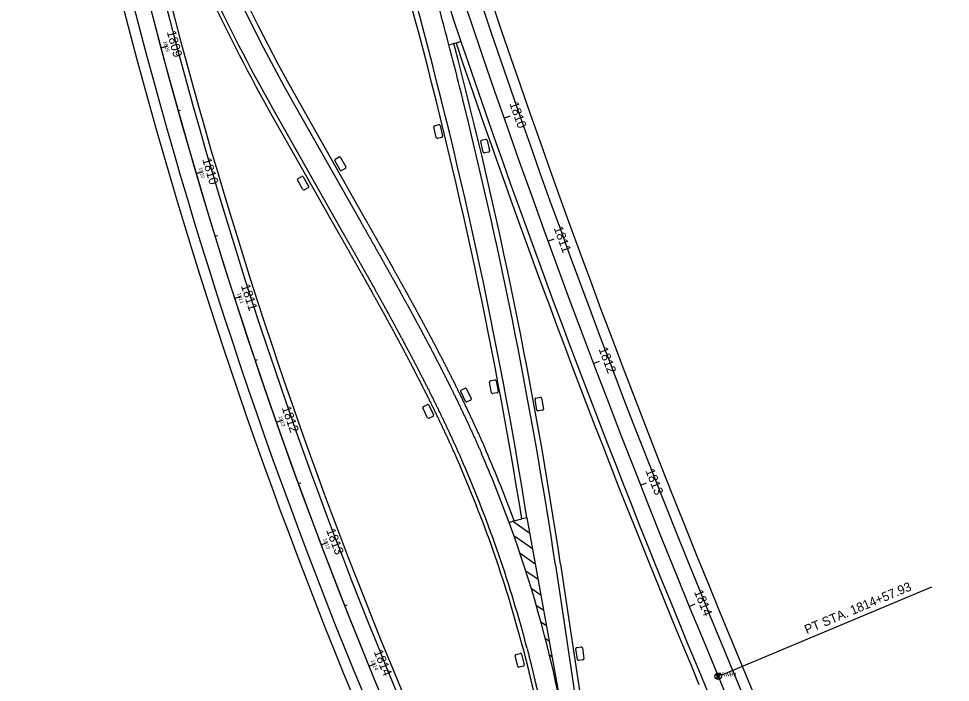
# Model space of a CAD drawing. Extents: x 8527 to 36635, y 12099 to 39012.
# Drawn here: x 20646 to 21360, y 34779 to 35288 of the extents above; entities that cross this region are included whole.
import ezdxf

# ---------------------------------------------------------------- set-up
doc = ezdxf.new("R2010")
doc.units = 0
for name, color, linetype in [('DR_P_Inlet_Protection', 7, 'Continuous'), ('GE_X_CL_20', 7, 'Continuous'), ('GK_Visualization', 7, 'Continuous'), ('MT_P_Dotted_Line', 7, 'Continuous'), ('MT_P_Text', 7, 'Continuous'), ('MT_P_Traffic_Attenuator', 7, 'Continuous'), ('PM_P_Transverse_Line', 7, 'Continuous'), ('PV_X_EOP', 7, 'Continuous'), ('PV_X_Shoulder', 7, 'Continuous'), ('SH_Cut_Line', 7, 'Continuous'), ('SH_Text', 7, 'Continuous')]:
    doc.layers.add(name, color=color, linetype=linetype)

msp = doc.modelspace()

# ---------------------------------------------------------------- linework, layer by layer
at = {"layer": 'DR_P_Inlet_Protection'}
msp.add_line((21182.19, 34784.02), (22003.54, 32822.13), dxfattribs=at)
for centre, radius, start, end in [((28229.01, 37734.18), 7639.44, 189.175, 202.716667), ((24529.94, 36271.9), 3906.53, 186.21667, 209.21667), ((24529.94, 36271.9), 3906.53, 191.33607, 209.21667)]:
    msp.add_arc(centre, radius, start, end, dxfattribs=at)
at = {"layer": 'GE_X_CL_20'}
for p, q in [((20755.34, 35265.23), (20757.27, 35265.75)), ((20768.53, 35217), (20770.46, 35217.55)), ((20782.34, 35168.95), (20784.26, 35169.51)), ((20796.76, 35121.08), (20798.68, 35121.67)), ((20811.8, 35073.39), (20813.7, 35074)), ((20827.44, 35025.9), (20829.34, 35026.54)), ((20843.69, 34978.62), (20845.58, 34979.28)), ((20860.55, 34931.54), (20862.43, 34932.23)), ((20878, 34884.69), (20879.87, 34885.4)), ((20896.06, 34838.06), (20897.92, 34838.8)), ((20914.71, 34791.67), (20916.56, 34792.43))]:
    msp.add_line(p, q, dxfattribs=at)
at = {"layer": 'GK_Visualization'}
for p, q in [((21183.75, 34784.02), (21180.63, 34784.02)), ((21180.86, 34782.69), (21183.53, 34785.36)), ((21180.86, 34785.36), (21183.53, 34782.69)), ((21182.19, 34785.58), (21182.19, 34782.46)), ((21182.19, 34784.02), (21938.59, 32977.27))]:
    msp.add_line(p, q, dxfattribs=at)
msp.add_arc((28229.01, 37734.18), 7639.44, 189.175, 202.716667, dxfattribs=at)
msp.add_arc((28229.01, 37734.18), 7639.44, 189.175, 202.716667, dxfattribs=at)
at = {"layer": 'MT_P_Dotted_Line'}
msp.add_line((21035.74, 34905.29), (21061.45, 34762.43), dxfattribs=at)
msp.add_arc((20125.43, 34573.33), 954.93, 11.42127, 20.11867, dxfattribs=at)
at = {"layer": 'MT_P_Text'}
for p, q in [((20755.34, 35265.23), (20760.17, 35266.52)), ((20782.34, 35168.95), (20787.14, 35170.36)), ((20811.8, 35073.39), (20816.56, 35074.92)), ((20843.69, 34978.62), (20848.41, 34980.27)), ((20878, 34884.69), (20882.68, 34886.46)), ((20914.71, 34791.67), (20919.33, 34793.57)), ((21182.19, 34784.02), (21938.59, 32977.27))]:
    msp.add_line(p, q, dxfattribs=at)
for centre, radius, start, end in [((28229.01, 37734.18), 7639.44, 189.175, 202.716667), ((24529.94, 36271.9), 3906.53, 186.21667, 209.21667)]:
    msp.add_arc(centre, radius, start, end, dxfattribs=at)
at = {"layer": 'MT_P_Traffic_Attenuator'}
for p, q in [((20981.38, 35268.89), (20979.81, 35268.47)), ((20861.46, 35223.01), (20911.92, 35133.96)), ((20841.45, 35211.67), (20891.91, 35122.62)), ((21035.74, 34905.29), (21031.79, 34904.66)), ((21022.09, 34901.79), (21025.84, 34903.17)), ((21061.5, 34869.77), (21067.12, 34832.37)), ((21067.12, 34832.37), (21100.09, 34612.83)), ((21200.64, 34791.75), (22021.99, 32829.86))]:
    msp.add_line(p, q, dxfattribs=at)
for centre, radius, start, end in [((28229.01, 37734.18), 7619.44, 191.815419, 202.716667), ((22104.16, 35927.29), 1428.39, 188.08556, 209.54167), ((24529.94, 36271.9), 3926.53, 191.34141, 209.21667), ((24529.94, 36271.9), 3890.53, 192.86631, 209.21667), ((22104.16, 35927.29), 1451.39, 200.88855, 209.54167), ((17264.37, 34299.46), 3815.72, 9.126, 15.41472), ((17264.37, 34299.46), 3839.72, 8.54167, 14.61747), ((28229.01, 37734.18), 7655.44, 198.78578, 202.716667), ((20125.43, 34573.33), 958.93, 20.11867, 23.54167), ((20111.51, 34565.44), 951.93, 14.54167, 23.54167)]:
    msp.add_arc(centre, radius, start, end, dxfattribs=at)
for points in [[(20911.92, 35133.96), (20913.25, 35131.61), (20914.59, 35129.26), (20915.92, 35126.91), (20917.25, 35124.56), (20918.58, 35122.21), (20919.92, 35119.85), (20921.25, 35117.5), (20922.58, 35115.15), (20923.91, 35112.79), (20925.24, 35110.44), (20926.56, 35108.08), (20927.89, 35105.72), (20929.22, 35103.37), (20930.54, 35101.01), (20931.87, 35098.65), (20933.19, 35096.29), (20934.51, 35093.93), (20935.83, 35091.57), (20937.15, 35089.21), (20938.47, 35086.84), (20939.78, 35084.48), (20941.1, 35082.11), (20942.41, 35079.75), (20943.72, 35077.38), (20945.03, 35075.01), (20946.33, 35072.64), (20947.63, 35070.26), (20948.93, 35067.89), (20950.23, 35065.51), (20951.53, 35063.14), (20952.82, 35060.76), (20954.11, 35058.38), (20955.4, 35056), (20956.68, 35053.61), (20957.96, 35051.23), (20959.24, 35048.84), (20960.52, 35046.45), (20961.79, 35044.06), (20963.05, 35041.66), (20964.32, 35039.27), (20965.58, 35036.87), (20966.84, 35034.47), (20968.09, 35032.07), (20969.34, 35029.67), (20970.59, 35027.26), (20971.83, 35024.85), (20973.07, 35022.44), (20974.3, 35020.03), (20975.53, 35017.61), (20976.75, 35015.19), (20977.97, 35012.77), (20979.19, 35010.35), (20980.4, 35007.93), (20981.6, 35005.5), (20982.8, 35003.07), (20984, 35000.63), (20985.19, 34998.2), (20986.38, 34995.76), (20987.56, 34993.32), (20988.73, 34990.87), (20989.9, 34988.43), (20991.06, 34985.98), (20992.22, 34983.52), (20993.37, 34981.07), (20994.52, 34978.61), (20995.66, 34976.15), (20996.79, 34973.68), (20997.92, 34971.21), (20999.04, 34968.74), (21000.15, 34966.27), (21001.26, 34963.79), (21002.36, 34961.31), (21003.46, 34958.83), (21004.54, 34956.35)], [(20891.91, 35122.62), (20893.24, 35120.27), (20894.58, 35117.92), (20895.91, 35115.57), (20897.24, 35113.22), (20898.57, 35110.87), (20899.9, 35108.52), (20901.23, 35106.16), (20902.56, 35103.81), (20903.89, 35101.46), (20905.22, 35099.11), (20906.55, 35096.75), (20907.87, 35094.4), (20909.2, 35092.05), (20910.52, 35089.69), (20911.84, 35087.34), (20913.16, 35084.98), (20914.48, 35082.62), (20915.8, 35080.27), (20917.12, 35077.91), (20918.43, 35075.55), (20919.74, 35073.19), (20921.06, 35070.83), (20922.36, 35068.47), (20923.67, 35066.1), (20924.97, 35063.74), (20926.28, 35061.38), (20927.58, 35059.01), (20928.87, 35056.64), (20930.17, 35054.27), (20931.46, 35051.9), (20932.75, 35049.53), (20934.03, 35047.16), (20935.32, 35044.78), (20936.6, 35042.41), (20937.87, 35040.03), (20939.15, 35037.65), (20940.42, 35035.27), (20941.68, 35032.89), (20942.95, 35030.5), (20944.21, 35028.12), (20945.46, 35025.73), (20946.72, 35023.34), (20947.96, 35020.95), (20949.21, 35018.55), (20950.45, 35016.16), (20951.68, 35013.76), (20952.92, 35011.36), (20954.14, 35008.96), (20955.37, 35006.55), (20956.58, 35004.15), (20957.8, 35001.74), (20959.01, 34999.33), (20960.21, 34996.92), (20961.41, 34994.5), (20962.61, 34992.08), (20963.79, 34989.66), (20964.98, 34987.24), (20966.16, 34984.82), (20967.33, 34982.39), (20968.5, 34979.96), (20969.66, 34977.53), (20970.81, 34975.09), (20971.97, 34972.65), (20973.11, 34970.21), (20974.25, 34967.77), (20975.38, 34965.32), (20976.51, 34962.88), (20977.63, 34960.42), (20978.74, 34957.97), (20979.85, 34955.51), (20980.95, 34953.05), (20982.04, 34950.59), (20983.13, 34948.13), (20984.21, 34945.65)], [(21032.94, 34804.46), (21033.61, 34801.85), (21034.28, 34799.24), (21034.94, 34796.62), (21035.59, 34794.01), (21036.23, 34791.39), (21036.87, 34788.77), (21037.5, 34786.15), (21038.12, 34783.53), (21038.74, 34780.91), (21039.35, 34778.28), (21039.96, 34775.66), (21040.56, 34773.03), (21041.15, 34770.4), (21041.73, 34767.77), (21042.31, 34765.13), (21042.89, 34762.5), (21043.46, 34759.86), (21044.02, 34757.23), (21044.57, 34754.59), (21045.13, 34751.95), (21045.67, 34749.31), (21046.21, 34746.67), (21046.75, 34744.02), (21047.28, 34741.38), (21047.8, 34738.73), (21048.32, 34736.09), (21048.84, 34733.44), (21049.35, 34730.79), (21049.85, 34728.14), (21050.36, 34725.49), (21050.85, 34722.84), (21051.35, 34720.19), (21051.83, 34717.53), (21052.32, 34714.88), (21052.8, 34712.22), (21053.27, 34709.57), (21053.75, 34706.91), (21054.22, 34704.25), (21054.68, 34701.6), (21055.14, 34698.94), (21055.6, 34696.28), (21056.05, 34693.62), (21056.51, 34690.96), (21056.95, 34688.29), (21057.4, 34685.63), (21057.84, 34682.97), (21058.28, 34680.3), (21058.72, 34677.64), (21059.15, 34674.98), (21059.58, 34672.31), (21060.01, 34669.65), (21060.44, 34666.98), (21060.87, 34664.31), (21061.29, 34661.65), (21061.71, 34658.98), (21062.13, 34656.31), (21062.54, 34653.64), (21062.96, 34650.97), (21063.37, 34648.3), (21063.78, 34645.63), (21064.19, 34642.96), (21064.6, 34640.29), (21065.01, 34637.62), (21065.42, 34634.95), (21065.82, 34632.28), (21066.23, 34629.61), (21066.63, 34626.94), (21067.04, 34624.27), (21067.44, 34621.6), (21067.84, 34618.92), (21068.24, 34616.25), (21068.65, 34613.58), (21069.05, 34610.91), (21069.45, 34608.23)]]:
    msp.add_spline(points, degree=3, dxfattribs=at)
at = {"layer": 'PM_P_Transverse_Line'}
for p, q in [((21037.87, 34893.48), (21024.59, 34902.71)), ((21039.99, 34881.67), (21025.77, 34891.56)), ((21042.12, 34869.86), (21030.46, 34877.96)), ((21044.24, 34858.05), (21034.86, 34864.57)), ((21046.37, 34846.24), (21038.98, 34851.38)), ((21048.49, 34834.43), (21042.84, 34838.36)), ((21050.62, 34822.62), (21046.45, 34825.51)), ((21052.74, 34810.81), (21049.83, 34812.83)), ((21054.86, 34799), (21052.99, 34800.31))]:
    msp.add_line(p, q, dxfattribs=at)
at = {"layer": 'PV_X_EOP'}
msp.add_arc((17264.37, 34299.46), 3835.72, 14.61747, 15.41472, dxfattribs=at)
at = {"layer": 'PV_X_Shoulder'}
for points in [[(20966.24, 35196.54), (20964.28, 35204.64)], [(20964.89, 35205.64), (20968.13, 35206.42)], [(20969.14, 35205.81), (20971.1, 35197.71)], [(20970.48, 35196.71), (20967.24, 35195.92)], [(21002.19, 35185.35), (21000.31, 35193.47)], [(21000.94, 35194.47), (21004.19, 35195.22)], [(21005.19, 35194.6), (21007.06, 35186.48)], [(21006.44, 35185.48), (21003.19, 35184.73)], [(20892.63, 35171.63), (20888.59, 35178.92)], [(20888.92, 35180.05), (20891.83, 35181.67)], [(20892.96, 35181.34), (20897, 35174.05)], [(20896.68, 35172.92), (20893.76, 35171.31)], [(20864.15, 35156.8), (20860.05, 35164.05)], [(20860.36, 35165.19), (20863.27, 35166.83)], [(20864.4, 35166.51), (20868.51, 35159.26)], [(20868.19, 35158.13), (20865.29, 35156.48)], [(21007.77, 35010.34), (21011.05, 35010.95)], [(20985.34, 35003.18), (20988.35, 35004.61)], [(20989.46, 35004.22), (20993.05, 34996.7)], [(21008.62, 35001.17), (21007.1, 35009.37)], [(21012.02, 35010.28), (21013.54, 35002.08)], [(20988.54, 34994.54), (20984.95, 35002.06)], [(21012.87, 35001.11), (21009.59, 35000.51)], [(21042.6, 34997.06), (21045.88, 34997.64)], [(21046.85, 34996.96), (21048.3, 34988.76)], [(20959.61, 34982.01), (20956.02, 34989.53)], [(20956.42, 34990.64), (20959.43, 34992.08)], [(20960.54, 34991.68), (20964.12, 34984.16)], [(20992.66, 34995.58), (20989.65, 34994.15)], [(21043.37, 34987.89), (21041.93, 34996.09)], [(20963.73, 34983.05), (20960.72, 34981.62)], [(21047.62, 34987.79), (21044.34, 34987.21)], [(21074.36, 34796.84), (21073.2, 34805.09)], [(21073.91, 34806.04), (21077.21, 34806.5)], [(21078.15, 34805.79), (21079.31, 34797.54)], [(21028.71, 34791.7), (21026.77, 34799.8)], [(21027.38, 34800.8), (21030.62, 34801.58)], [(21031.63, 34800.97), (21033.57, 34792.86)], [(21078.6, 34796.6), (21075.3, 34796.13)], [(21032.96, 34791.86), (21029.72, 34791.08)]]:
    msp.add_lwpolyline(points, dxfattribs=at)
for centre, start, end in [((20965.09, 35204.83), 103.6, 193.6), ((20968.33, 35205.61), 13.6, 103.6), ((20967.05, 35196.73), 193.6, 283.6), ((20970.29, 35197.52), 283.6, 13.6), ((21001.13, 35193.66), 103, 193), ((21004.37, 35194.41), 13, 103), ((21003, 35185.54), 193, 283), ((21006.25, 35186.29), 283, 13), ((20889.32, 35179.32), 119, 209), ((20892.24, 35180.94), 29, 119), ((20893.36, 35172.03), 209, 299), ((20896.28, 35173.65), 299, 29), ((20860.78, 35164.46), 119.5, 209.5), ((20863.68, 35166.1), 29.5, 119.5), ((20864.88, 35157.21), 209.5, 299.5), ((20867.78, 35158.85), 299.5, 29.5), ((21011.2, 35010.13), 10.5, 100.5), ((20988.71, 35003.86), 25.5, 115.5), ((21007.92, 35009.52), 100.5, 190.5), ((20985.7, 35002.42), 115.5, 205.5), ((20992.3, 34996.34), 295.5, 25.5), ((21009.44, 35001.33), 190.5, 280.5), ((21012.72, 35001.93), 280.5, 10.5), ((21042.75, 34996.24), 100, 190), ((21046.03, 34996.82), 10, 100), ((20956.78, 34989.89), 115.5, 205.5), ((20959.78, 34991.33), 25.5, 115.5), ((20989.29, 34994.9), 205.5, 295.5), ((20963.37, 34983.8), 295.5, 25.5), ((21044.19, 34988.03), 190, 280), ((21047.48, 34988.61), 280, 10), ((20960.36, 34982.37), 205.5, 295.5), ((21074.03, 34805.21), 98, 188), ((21077.33, 34805.67), 8, 98), ((21027.58, 34799.99), 103.5, 193.5), ((21030.82, 34800.77), 13.5, 103.5), ((21075.19, 34796.96), 188, 278), ((21078.49, 34797.42), 278, 8), ((21029.52, 34791.89), 193.5, 283.5), ((21032.76, 34792.67), 283.5, 13.5)]:
    msp.add_arc(centre, 0.833, start, end, dxfattribs=at)
at = {"layer": 'SH_Cut_Line'}
for p, q in [((21018.11, 35211.47), (21022.83, 35213.13)), ((21051.75, 35117.3), (21056.45, 35119.02)), ((21086.62, 35023.58), (21091.3, 35025.35)), ((21122.71, 34930.32), (21127.37, 34932.16)), ((21184.5, 34784.99), (21345.89, 34852.56)), ((21160.02, 34837.54), (21164.65, 34839.44))]:
    msp.add_line(p, q, dxfattribs=at)
msp.add_circle((21182.19, 34784.02), 2.5, dxfattribs=at)
at = {"layer": 'SH_Text'}
for p, q in [((20975.94, 35267.46), (20979.81, 35268.47)), ((20985.17, 35270.18), (20981.38, 35268.89)), ((20857.98, 35221.03), (20908.44, 35131.99)), ((20844.06, 35213.15), (20894.52, 35124.1)), ((21025.84, 34903.17), (21031.79, 34904.66)), ((21057.55, 34869.18), (21063.16, 34831.77)), ((21063.16, 34831.77), (21096.14, 34612.23)), ((21193.26, 34788.66), (22014.61, 32826.77)), ((21171.12, 34779.39), (21992.47, 32817.5))]:
    msp.add_line(p, q, dxfattribs=at)
for centre, radius, start, end in [((28229.01, 37734.18), 7627.44, 191.807877, 202.716667), ((22104.16, 35927.29), 1432.39, 188.08556, 209.54167), ((24529.94, 36271.9), 3918.53, 191.33607, 209.21667), ((28229.01, 37734.18), 7651.44, 197.265545, 198.78578), ((22104.16, 35927.29), 1448.39, 200.88855, 209.54167), ((24531.79, 36272.61), 3896.49, 192.87045, 209.21252), ((17264.37, 34299.46), 3819.72, 9.126, 15.41472), ((28229.01, 37734.18), 7651.44, 198.78578, 202.716667), ((17264.37, 34299.46), 3835.72, 13.90526, 14.61747), ((17264.37, 34299.46), 3835.72, 8.54167, 13.90526), ((20125.43, 34573.33), 954.93, 20.11867, 23.54167), ((20111.51, 34565.44), 954.93, 14.54167, 23.54167)]:
    msp.add_arc(centre, radius, start, end, dxfattribs=at)
for points in [[(20908.44, 35131.99), (20909.77, 35129.64), (20911.11, 35127.29), (20912.44, 35124.94), (20913.77, 35122.59), (20915.1, 35120.23), (20916.43, 35117.88), (20917.76, 35115.53), (20919.09, 35113.18), (20920.42, 35110.82), (20921.75, 35108.47), (20923.08, 35106.12), (20924.41, 35103.76), (20925.73, 35101.41), (20927.06, 35099.05), (20928.38, 35096.69), (20929.7, 35094.34), (20931.02, 35091.98), (20932.34, 35089.62), (20933.66, 35087.26), (20934.97, 35084.9), (20936.29, 35082.54), (20937.6, 35080.17), (20938.91, 35077.81), (20940.22, 35075.44), (20941.52, 35073.08), (20942.82, 35070.71), (20944.13, 35068.34), (20945.42, 35065.97), (20946.72, 35063.6), (20948.01, 35061.22), (20949.3, 35058.85), (20950.59, 35056.47), (20951.88, 35054.1), (20953.16, 35051.72), (20954.44, 35049.34), (20955.71, 35046.95), (20956.98, 35044.57), (20958.25, 35042.18), (20959.52, 35039.79), (20960.78, 35037.4), (20962.04, 35035.01), (20963.29, 35032.62), (20964.54, 35030.22), (20965.79, 35027.82), (20967.03, 35025.42), (20968.27, 35023.02), (20969.51, 35020.62), (20970.74, 35018.21), (20971.96, 35015.8), (20973.18, 35013.39), (20974.4, 35010.98), (20975.61, 35008.56), (20976.82, 35006.14), (20978.02, 35003.72), (20979.22, 35001.3), (20980.41, 34998.87), (20981.59, 34996.44), (20982.78, 34994.01), (20983.95, 34991.58), (20985.12, 34989.14), (20986.29, 34986.71), (20987.45, 34984.26), (20988.6, 34981.82), (20989.75, 34979.37), (20990.89, 34976.92), (20992.02, 34974.47), (20993.15, 34972.01), (20994.28, 34969.56), (20995.39, 34967.1), (20996.5, 34964.63), (20997.61, 34962.16), (20998.7, 34959.69), (20999.79, 34957.22), (21000.88, 34954.74)], [(20894.52, 35124.1), (20895.85, 35121.75), (20897.19, 35119.4), (20898.52, 35117.05), (20899.85, 35114.7), (20901.18, 35112.35), (20902.51, 35109.99), (20903.84, 35107.64), (20905.17, 35105.29), (20906.5, 35102.94), (20907.83, 35100.58), (20909.16, 35098.23), (20910.49, 35095.87), (20911.81, 35093.52), (20913.14, 35091.16), (20914.46, 35088.8), (20915.78, 35086.45), (20917.1, 35084.09), (20918.42, 35081.73), (20919.74, 35079.37), (20921.05, 35077.01), (20922.37, 35074.65), (20923.68, 35072.28), (20924.99, 35069.92), (20926.3, 35067.55), (20927.6, 35065.19), (20928.9, 35062.82), (20930.21, 35060.45), (20931.5, 35058.08), (20932.8, 35055.71), (20934.09, 35053.34), (20935.38, 35050.96), (20936.67, 35048.59), (20937.96, 35046.21), (20939.24, 35043.83), (20940.52, 35041.45), (20941.79, 35039.06), (20943.06, 35036.68), (20944.33, 35034.29), (20945.6, 35031.91), (20946.86, 35029.51), (20948.12, 35027.12), (20949.37, 35024.73), (20950.62, 35022.33), (20951.87, 35019.94), (20953.11, 35017.53), (20954.35, 35015.13), (20955.59, 35012.73), (20956.82, 35010.32), (20958.04, 35007.91), (20959.26, 35005.5), (20960.48, 35003.09), (20961.69, 35000.67), (20962.9, 34998.25), (20964.1, 34995.83), (20965.3, 34993.41), (20966.49, 34990.98), (20967.67, 34988.56), (20968.86, 34986.13), (20970.03, 34983.69), (20971.2, 34981.26), (20972.37, 34978.82), (20973.53, 34976.38), (20974.68, 34973.93), (20975.83, 34971.48), (20976.97, 34969.03), (20978.1, 34966.58), (20979.23, 34964.13), (20980.36, 34961.67), (20981.47, 34959.21), (20982.58, 34956.74), (20983.69, 34954.27), (20984.78, 34951.8), (20985.87, 34949.33), (20986.96, 34946.86)], [(21035.84, 34805.21), (21036.52, 34802.59), (21037.19, 34799.97), (21037.85, 34797.35), (21038.5, 34794.73), (21039.15, 34792.11), (21039.79, 34789.48), (21040.42, 34786.85), (21041.04, 34784.22), (21041.66, 34781.59), (21042.28, 34778.96), (21042.88, 34776.33), (21043.48, 34773.69), (21044.08, 34771.05), (21044.66, 34768.42), (21045.24, 34765.78), (21045.82, 34763.13), (21046.39, 34760.49), (21046.95, 34757.85), (21047.51, 34755.21), (21048.06, 34752.56), (21048.61, 34749.91), (21049.15, 34747.26), (21049.69, 34744.62), (21050.22, 34741.97), (21050.75, 34739.31), (21051.27, 34736.66), (21051.78, 34734.01), (21052.29, 34731.36), (21052.8, 34728.7), (21053.3, 34726.05), (21053.8, 34723.39), (21054.3, 34720.73), (21054.78, 34718.07), (21055.27, 34715.42), (21055.75, 34712.76), (21056.23, 34710.1), (21056.7, 34707.43), (21057.17, 34704.77), (21057.64, 34702.11), (21058.1, 34699.45), (21058.56, 34696.78), (21059.01, 34694.12), (21059.46, 34691.46), (21059.91, 34688.79), (21060.36, 34686.12), (21060.8, 34683.46), (21061.24, 34680.79), (21061.68, 34678.12), (21062.11, 34675.46), (21062.55, 34672.79), (21062.98, 34670.12), (21063.4, 34667.45), (21063.83, 34664.78), (21064.25, 34662.11), (21064.67, 34659.44), (21065.09, 34656.77), (21065.51, 34654.1), (21065.92, 34651.43), (21066.34, 34648.76), (21066.75, 34646.09), (21067.16, 34643.42), (21067.57, 34640.75), (21067.98, 34638.08), (21068.38, 34635.4), (21068.79, 34632.73), (21069.2, 34630.06), (21069.6, 34627.39), (21070, 34624.72), (21070.41, 34622.04), (21070.81, 34619.37), (21071.21, 34616.7), (21071.61, 34614.03), (21072.01, 34611.35), (21072.42, 34608.68)]]:
    msp.add_spline(points, degree=3, dxfattribs=at)

# ---------------------------------------------------------------- texts
at = {"layer": 'GE_X_CL_20'}
for s, rotation, p in [('1809', 284.93289, (20757.13, 35270.14)), ('1810', 286.39956, (20784.19, 35173.3)), ('1811', 287.86623, (20813.7, 35077.28)), ('1812', 289.33289, (20845.34, 34982.99)), ('1813', 290.79956, (20879.52, 34889.13)), ('1814', 292.26623, (20916.13, 34796.11))]:
    msp.add_text(s, height=2.8, rotation=rotation, dxfattribs=at).set_placement(p)
at = {"layer": 'GK_Visualization'}
msp.add_text('PRWB4', height=2.8, dxfattribs=at).set_placement((21182.19, 34784.02))
at = {"layer": 'MT_P_Text'}
for s, rotation, p in [('1809', 284.93289, (20759.83, 35277.49)), ('1810', 286.39956, (20786.96, 35179.81)), ('1811', 287.86623, (20816.55, 35083.11)), ('1812', 289.33289, (20847.81, 34989.55)), ('1813', 290.79956, (20881.81, 34895.8)), ('1814', 292.26623, (20918.26, 34802.77))]:
    msp.add_text(s, height=7, rotation=rotation, dxfattribs=at).set_placement(p)
at = {"layer": 'SH_Cut_Line'}
for s, rotation, p in [('1810', 289.28221, (21022.18, 35222.56)), ('1811', 290.03221, (21056.13, 35127.19)), ('1812', 290.78221, (21090.46, 35034.61)), ('1813', 291.53221, (21126.37, 34941.48)), ('PT STA. 1814+57.93', 22.71667, (21250.02, 34816.22)), ('1814', 292.28221, (21163.58, 34848.65))]:
    msp.add_text(s, height=7, rotation=rotation, dxfattribs=at).set_placement(p)

doc.saveas('drawing.dxf')
